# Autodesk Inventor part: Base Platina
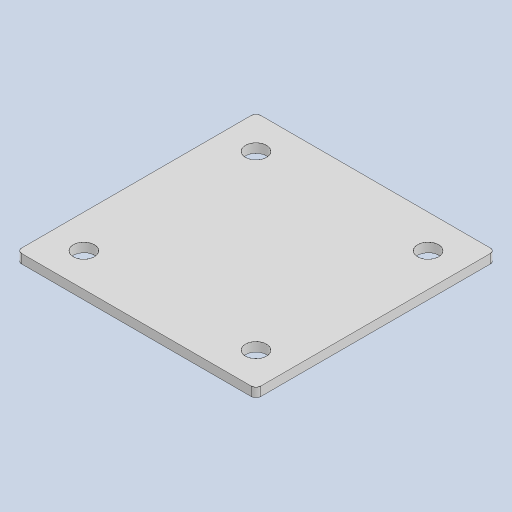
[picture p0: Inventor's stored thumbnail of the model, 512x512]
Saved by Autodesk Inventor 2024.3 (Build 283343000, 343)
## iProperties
Created: 2025-10
Part Number: Base Platina
Material: Genérico
Document SubType Name: Modeling
Designer: Asus
Density: 1 g/cm^3
Appearance: Valor por defecto
Author: Asus
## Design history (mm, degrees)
sketch "Boceto1"
  geometry: L1 (-125, -125)-(125, -125); L2 (125, -125)-(125, 125); L3 (125, 125)-(-125, 125); L4 (-125, 125)-(-125, -125); L5 (-125, -125)-(125, 125); L6 (125, -125)-(-125, 125); 1 further point
  constraints: 12 end point, 2 midpoint, 2 parallel, 1 horizontal, 1 perpendicular
  dimensions: "d0" = 250 distance of L1.end L2.end; "d1" = 250 distance of L1.start L1.end (= d0)
extrude "Extrusión1" new body sketch "Boceto1" distance "d2" = 9.525; taper "d3" = 0 deg
sketch "Boceto2"
  geometry: L1 (90, 90)-(-90, 90); L2 (-90, 90)-(-90, -90); L3 (-90, -90)-(90, -90); L4 (90, -90)-(90, 90); L5 (90, 90)-(-90, -90); L6 (-90, 90)-(90, -90); C1 r 84.138 at (0, 0); 5 further points
  constraints: 12 end point, 5 coincident, 2 midpoint, 2 parallel, 1 centre point, 1 horizontal, 1 perpendicular
  dimensions: "d4" = 168.275 diameter of C1; "d5" = 180 distance of L1.end L2.end (= d6); "d6" = 180 distance of L1.start L1.end
hole "Agujero1" sketch "Boceto2" at (-90, -90), (-90, 90), (90, 90), (90, -90) diameter "d7" = 22; stored, may be unused: countersink angle "d11" = 90 deg, drill point angle "d13" = 118 deg; dims "d8" = 6, "d9" = 4, "d10" = 2, "d12" = 8
fillet "Empalme1" dims "d14" = 5
node "Sólido1"
